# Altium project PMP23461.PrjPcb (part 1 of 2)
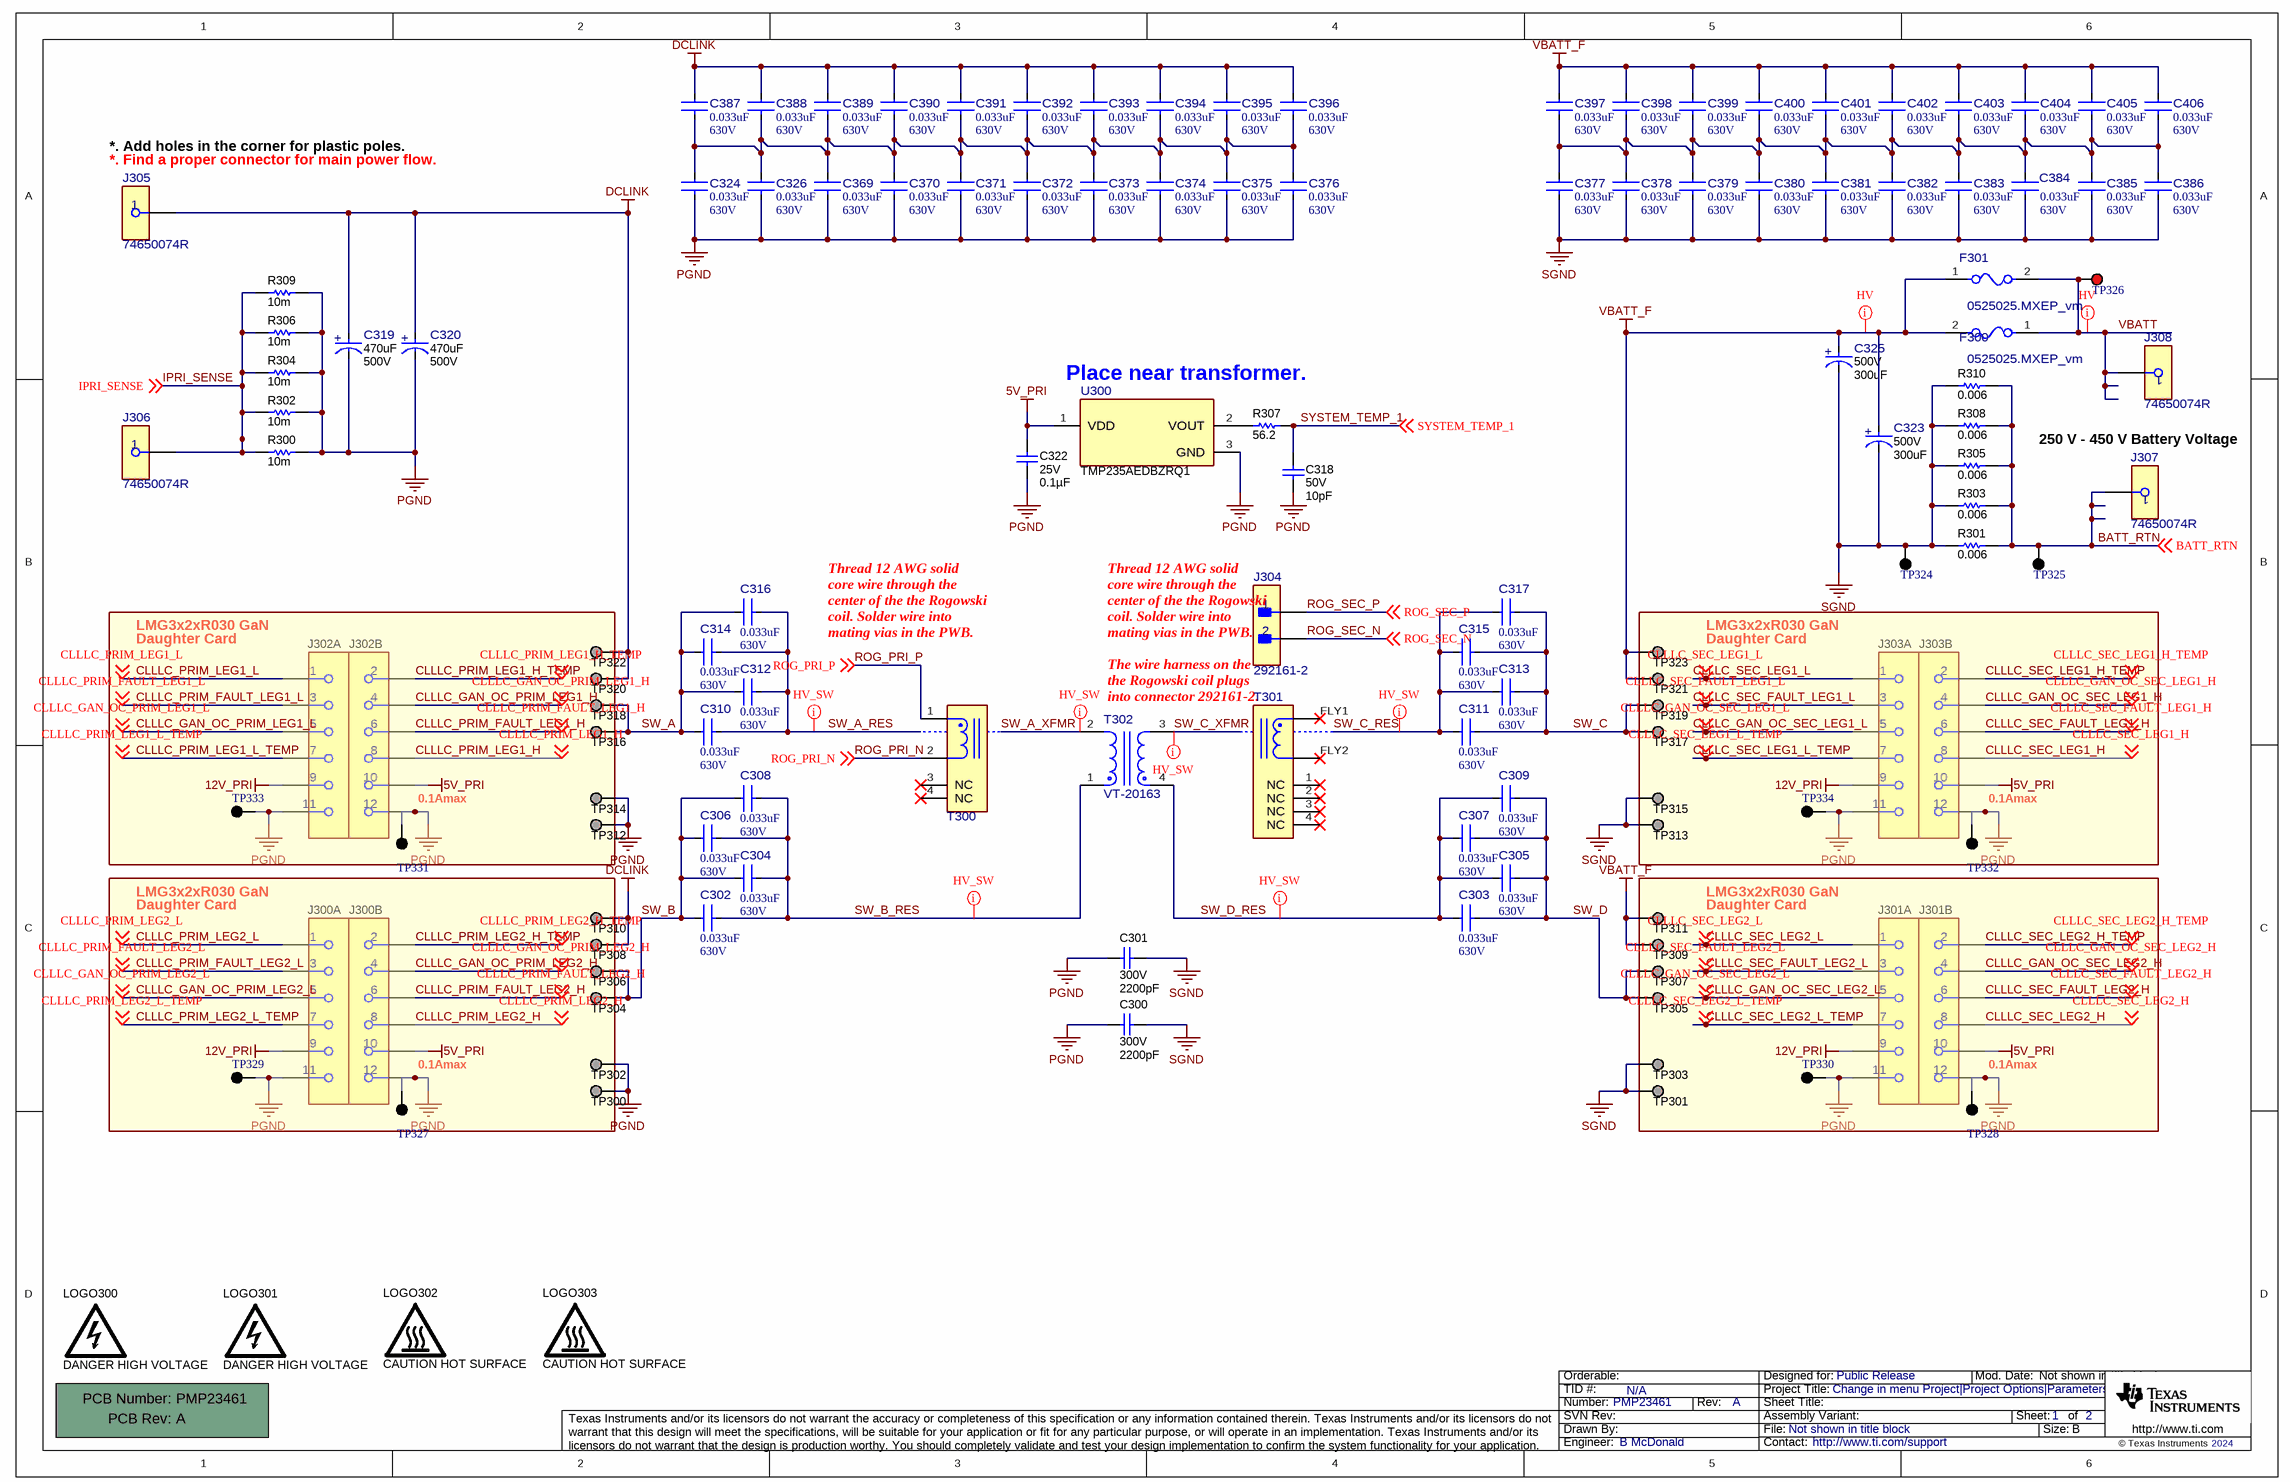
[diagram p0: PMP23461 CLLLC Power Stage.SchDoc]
CopyrightYear: 2024; PCB_Layout: Sean Yu; PCB_Rev: A; PRJ_Customer: Public Release; PRJ_Engineer: B McDonald; PRJ_Number: PMP23461; PRJ_Title: Change in menu Project|Project Options|Parameters; SCH_Rev: A; TechSupport: http://www.ti.com/support; TID: N/A
2 sheets, 242 parts. Net scope: global (net labels, ports and power ports of the same name join across sheets).
Board file: PMP23461 PCB.PcbDoc
Sheets:
  PMP23461 CLLLC Power Stage.SchDoc
  PMP23461 CLLLC Sensing.SchDoc

## Sheet PMP23461 CLLLC Power Stage.SchDoc
size 431 x 279 mm; Date: Not shown in title block; ApprovedBy: Not shown in title block; CheckedBy: Not shown in title block; Author: Not shown in title block; CompanyName: Not shown in title block; Engineer: Not shown in title block; Organization: Not shown in title block; Address1: Not shown in title block; Address2: Not shown in title block; Address3: Not shown in title block; Address4: Not shown in title block; DocumentNumber: 1; Revision: Use project parameter SCH_Rev; SheetNumber: 1; SheetTotal: 2; PageSetup: Record=PageOptions¦CenterHorizontal=True¦CenterVertical=True¦PrintScale=1.00¦XCorrection=1.00¦YCorrection=1.00¦PrintKind=0¦BorderSize=5000000¦LeftOffset=0¦BottomOffset=0¦Orientation=2¦PaperLength=1000¦PaperWidth=1000¦Scale=100¦PaperSource=15¦PrintQuality=600¦MediaType=1¦DitherType=10¦PaperKind=Letter¦PrintScaleMode=1

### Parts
!PCB300  Printed Circuit Board  (value not drawn)  (mechanical)
C300  VDC_V: 300V  ValueDisplayed: 2200pF  [AY2_950x500_Straight]  (hidden comment: AY2222M35Y5US63L7)
C301  VDC_V: 300V  ValueDisplayed: 2200pF  [AY2_950x500_Straight]  (hidden comment: AY2222M35Y5US63L7)
C302  ValueDisplayed: 0.033uF  VDC_V: 630V  [FP-C1210X333JBGACAUTO_1210-MFG]  (hidden comment: CGA6P4C0G2J333J250AA)
C303  ValueDisplayed: 0.033uF  VDC_V: 630V  [FP-C1210X333JBGACAUTO_1210-MFG]  (hidden comment: CGA6P4C0G2J333J250AA)
C304  ValueDisplayed: 0.033uF  VDC_V: 630V  [FP-C1210X333JBGACAUTO_1210-MFG]  (hidden comment: CGA6P4C0G2J333J250AA)
C305  ValueDisplayed: 0.033uF  VDC_V: 630V  [FP-C1210X333JBGACAUTO_1210-MFG]  (hidden comment: CGA6P4C0G2J333J250AA)
C306  ValueDisplayed: 0.033uF  VDC_V: 630V  [FP-C1210X333JBGACAUTO_1210-MFG]  (hidden comment: CGA6P4C0G2J333J250AA)
C307  ValueDisplayed: 0.033uF  VDC_V: 630V  [FP-C1210X333JBGACAUTO_1210-MFG]  (hidden comment: CGA6P4C0G2J333J250AA)
C308  ValueDisplayed: 0.033uF  VDC_V: 630V  [FP-C1210X333JBGACAUTO_1210-MFG]  (hidden comment: CGA6P4C0G2J333J250AA)
C309  ValueDisplayed: 0.033uF  VDC_V: 630V  [FP-C1210X333JBGACAUTO_1210-MFG]  (hidden comment: CGA6P4C0G2J333J250AA)
C310  ValueDisplayed: 0.033uF  VDC_V: 630V  [FP-C1210X333JBGACAUTO_1210-MFG]  (hidden comment: CGA6P4C0G2J333J250AA)
C311  ValueDisplayed: 0.033uF  VDC_V: 630V  [FP-C1210X333JBGACAUTO_1210-MFG]  (hidden comment: CGA6P4C0G2J333J250AA)
C312  ValueDisplayed: 0.033uF  VDC_V: 630V  [FP-C1210X333JBGACAUTO_1210-MFG]  (hidden comment: CGA6P4C0G2J333J250AA)
C313  ValueDisplayed: 0.033uF  VDC_V: 630V  [FP-C1210X333JBGACAUTO_1210-MFG]  (hidden comment: CGA6P4C0G2J333J250AA)
C314  ValueDisplayed: 0.033uF  VDC_V: 630V  [FP-C1210X333JBGACAUTO_1210-MFG]  (hidden comment: CGA6P4C0G2J333J250AA)
C315  ValueDisplayed: 0.033uF  VDC_V: 630V  [FP-C1210X333JBGACAUTO_1210-MFG]  (hidden comment: CGA6P4C0G2J333J250AA)
C316  ValueDisplayed: 0.033uF  VDC_V: 630V  [FP-C1210X333JBGACAUTO_1210-MFG]  (hidden comment: CGA6P4C0G2J333J250AA)
C317  ValueDisplayed: 0.033uF  VDC_V: 630V  [FP-C1210X333JBGACAUTO_1210-MFG]  (hidden comment: CGA6P4C0G2J333J250AA)
C318  VDC_V: 50V  ValueDisplayed: 10pF  [0402]  (hidden comment: 04025U100CAT2A)
C319  ValueDisplayed: 470uF  VDC_V: 500V  [FP-ALA7DA471DE500_RADIAL-MFG]  (hidden comment: B43649A6477M057)
C320  ValueDisplayed: 470uF  VDC_V: 500V  [FP-ALA7DA471DE500_RADIAL-MFG]  (hidden comment: B43649A6477M057)
C322  VDC_V: 25V  ValueDisplayed: 0.1µF  [0402]  (hidden comment: CGA2B3X7R1E104K050BB)
C323  VDC_V: 500V  ValueDisplayed: 300uF  [FP-ALA8DA301CF500_RADIAL-MFG]  (hidden comment: B43649A6337M057)
C324  ValueDisplayed: 0.033uF  VDC_V: 630V  [FP-C1210X333JBGACAUTO_1210-MFG]  (hidden comment: CGA6P4C0G2J333J250AA)
C325  VDC_V: 500V  ValueDisplayed: 300uF  [FP-ALA8DA301CF500_RADIAL-MFG]  (hidden comment: B43649A6337M057)
C326  ValueDisplayed: 0.033uF  VDC_V: 630V  [FP-C1210X333JBGACAUTO_1210-MFG]  (hidden comment: CGA6P4C0G2J333J250AA)
C369  ValueDisplayed: 0.033uF  VDC_V: 630V  [FP-C1210X333JBGACAUTO_1210-MFG]  (hidden comment: CGA6P4C0G2J333J250AA)
C370  ValueDisplayed: 0.033uF  VDC_V: 630V  [FP-C1210X333JBGACAUTO_1210-MFG]  (hidden comment: CGA6P4C0G2J333J250AA)
C371  ValueDisplayed: 0.033uF  VDC_V: 630V  [FP-C1210X333JBGACAUTO_1210-MFG]  (hidden comment: CGA6P4C0G2J333J250AA)
C372  ValueDisplayed: 0.033uF  VDC_V: 630V  [FP-C1210X333JBGACAUTO_1210-MFG]  (hidden comment: CGA6P4C0G2J333J250AA)
C373  ValueDisplayed: 0.033uF  VDC_V: 630V  [FP-C1210X333JBGACAUTO_1210-MFG]  (hidden comment: CGA6P4C0G2J333J250AA)
C374  ValueDisplayed: 0.033uF  VDC_V: 630V  [FP-C1210X333JBGACAUTO_1210-MFG]  (hidden comment: CGA6P4C0G2J333J250AA)
C375  ValueDisplayed: 0.033uF  VDC_V: 630V  [FP-C1210X333JBGACAUTO_1210-MFG]  (hidden comment: CGA6P4C0G2J333J250AA)
C376  ValueDisplayed: 0.033uF  VDC_V: 630V  [FP-C1210X333JBGACAUTO_1210-MFG]  (hidden comment: CGA6P4C0G2J333J250AA)
C377  ValueDisplayed: 0.033uF  VDC_V: 630V  [FP-C1210X333JBGACAUTO_1210-MFG]  (hidden comment: CGA6P4C0G2J333J250AA)
C378  ValueDisplayed: 0.033uF  VDC_V: 630V  [FP-C1210X333JBGACAUTO_1210-MFG]  (hidden comment: CGA6P4C0G2J333J250AA)
C379  ValueDisplayed: 0.033uF  VDC_V: 630V  [FP-C1210X333JBGACAUTO_1210-MFG]  (hidden comment: CGA6P4C0G2J333J250AA)
C380  ValueDisplayed: 0.033uF  VDC_V: 630V  [FP-C1210X333JBGACAUTO_1210-MFG]  (hidden comment: CGA6P4C0G2J333J250AA)
C381  ValueDisplayed: 0.033uF  VDC_V: 630V  [FP-C1210X333JBGACAUTO_1210-MFG]  (hidden comment: CGA6P4C0G2J333J250AA)
C382  ValueDisplayed: 0.033uF  VDC_V: 630V  [FP-C1210X333JBGACAUTO_1210-MFG]  (hidden comment: CGA6P4C0G2J333J250AA)
C383  ValueDisplayed: 0.033uF  VDC_V: 630V  [FP-C1210X333JBGACAUTO_1210-MFG]  (hidden comment: CGA6P4C0G2J333J250AA)
C384  ValueDisplayed: 0.033uF  VDC_V: 630V  [FP-C1210X333JBGACAUTO_1210-MFG]  (hidden comment: CGA6P4C0G2J333J250AA)
C385  ValueDisplayed: 0.033uF  VDC_V: 630V  [FP-C1210X333JBGACAUTO_1210-MFG]  (hidden comment: CGA6P4C0G2J333J250AA)
C386  ValueDisplayed: 0.033uF  VDC_V: 630V  [FP-C1210X333JBGACAUTO_1210-MFG]  (hidden comment: CGA6P4C0G2J333J250AA)
C387  ValueDisplayed: 0.033uF  VDC_V: 630V  [FP-C1210X333JBGACAUTO_1210-MFG]  (hidden comment: CGA6P4C0G2J333J250AA)
C388  ValueDisplayed: 0.033uF  VDC_V: 630V  [FP-C1210X333JBGACAUTO_1210-MFG]  (hidden comment: CGA6P4C0G2J333J250AA)
C389  ValueDisplayed: 0.033uF  VDC_V: 630V  [FP-C1210X333JBGACAUTO_1210-MFG]  (hidden comment: CGA6P4C0G2J333J250AA)
C390  ValueDisplayed: 0.033uF  VDC_V: 630V  [FP-C1210X333JBGACAUTO_1210-MFG]  (hidden comment: CGA6P4C0G2J333J250AA)
C391  ValueDisplayed: 0.033uF  VDC_V: 630V  [FP-C1210X333JBGACAUTO_1210-MFG]  (hidden comment: CGA6P4C0G2J333J250AA)
C392  ValueDisplayed: 0.033uF  VDC_V: 630V  [FP-C1210X333JBGACAUTO_1210-MFG]  (hidden comment: CGA6P4C0G2J333J250AA)
C393  ValueDisplayed: 0.033uF  VDC_V: 630V  [FP-C1210X333JBGACAUTO_1210-MFG]  (hidden comment: CGA6P4C0G2J333J250AA)
C394  ValueDisplayed: 0.033uF  VDC_V: 630V  [FP-C1210X333JBGACAUTO_1210-MFG]  (hidden comment: CGA6P4C0G2J333J250AA)
C395  ValueDisplayed: 0.033uF  VDC_V: 630V  [FP-C1210X333JBGACAUTO_1210-MFG]  (hidden comment: CGA6P4C0G2J333J250AA)
C396  ValueDisplayed: 0.033uF  VDC_V: 630V  [FP-C1210X333JBGACAUTO_1210-MFG]  (hidden comment: CGA6P4C0G2J333J250AA)
C397  ValueDisplayed: 0.033uF  VDC_V: 630V  [FP-C1210X333JBGACAUTO_1210-MFG]  (hidden comment: CGA6P4C0G2J333J250AA)
C398  ValueDisplayed: 0.033uF  VDC_V: 630V  [FP-C1210X333JBGACAUTO_1210-MFG]  (hidden comment: CGA6P4C0G2J333J250AA)
C399  ValueDisplayed: 0.033uF  VDC_V: 630V  [FP-C1210X333JBGACAUTO_1210-MFG]  (hidden comment: CGA6P4C0G2J333J250AA)
C400  ValueDisplayed: 0.033uF  VDC_V: 630V  [FP-C1210X333JBGACAUTO_1210-MFG]  (hidden comment: CGA6P4C0G2J333J250AA)
C401  ValueDisplayed: 0.033uF  VDC_V: 630V  [FP-C1210X333JBGACAUTO_1210-MFG]  (hidden comment: CGA6P4C0G2J333J250AA)
C402  ValueDisplayed: 0.033uF  VDC_V: 630V  [FP-C1210X333JBGACAUTO_1210-MFG]  (hidden comment: CGA6P4C0G2J333J250AA)
C403  ValueDisplayed: 0.033uF  VDC_V: 630V  [FP-C1210X333JBGACAUTO_1210-MFG]  (hidden comment: CGA6P4C0G2J333J250AA)
C404  ValueDisplayed: 0.033uF  VDC_V: 630V  [FP-C1210X333JBGACAUTO_1210-MFG]  (hidden comment: CGA6P4C0G2J333J250AA)
C405  ValueDisplayed: 0.033uF  VDC_V: 630V  [FP-C1210X333JBGACAUTO_1210-MFG]  (hidden comment: CGA6P4C0G2J333J250AA)
C406  ValueDisplayed: 0.033uF  VDC_V: 630V  [FP-C1210X333JBGACAUTO_1210-MFG]  (hidden comment: CGA6P4C0G2J333J250AA)
F300  0525025.MXEP_vm  [FP-0525025.MXEP_vm_AXIAL-MFG]
F301  0525025.MXEP_vm  [FP-0525025.MXEP_vm_AXIAL-MFG]
J300  HLE-106-02-G-DV-BE-A  [FP-HLE-106-02-G-DV-BE-A_HDR12-MFG]  (value not drawn)  (parts A,B of 2)
J301  HLE-106-02-G-DV-BE-A  [FP-HLE-106-02-G-DV-BE-A_HDR12-MFG]  (value not drawn)  (parts A,B of 2)
J302  HLE-106-02-G-DV-BE-A  [FP-HLE-106-02-G-DV-BE-A_HDR12-MFG]  (value not drawn)  (parts A,B of 2)
J303  HLE-106-02-G-DV-BE-A  [FP-HLE-106-02-G-DV-BE-A_HDR12-MFG]  (value not drawn)  (parts A,B of 2)
J304  292161-2  [FP-292161-2_HDR2-MFG]
J305  74650074R  [FP-74650074R_SCREW_MOUNTING-MFG]
J306  74650074R  [FP-74650074R_SCREW_MOUNTING-MFG]
J307  74650074R  [FP-74650074R_SCREW_MOUNTING-MFG]
J308  74650074R  [FP-74650074R_SCREW_MOUNTING-MFG]
LOGO300  DANGER HIGH VOLTAGE  [IEC_HighVoltage_Small]  (no BOM)
LOGO301  DANGER HIGH VOLTAGE  [IEC_HighVoltage_Small]  (no BOM)
LOGO302  CAUTION HOT SURFACE  [IEC_HotSurface_Small]  (no BOM)
LOGO303  CAUTION HOT SURFACE  [IEC_HotSurface_Small]  (no BOM)
R300  ValueDisplayed: 10m  [FP-CRF1206-FZ-R010ELF_1206-MFG]  (hidden comment: CRF1206-FZ-R010ELF)
R301  ValueDisplayed: 0.006  [1206]  (hidden comment: WSL12066L000FEA18)
R302  ValueDisplayed: 10m  [FP-CRF1206-FZ-R010ELF_1206-MFG]  (hidden comment: CRF1206-FZ-R010ELF)
R303  ValueDisplayed: 0.006  [1206]  (hidden comment: WSL12066L000FEA18)
R304  ValueDisplayed: 10m  [FP-CRF1206-FZ-R010ELF_1206-MFG]  (hidden comment: CRF1206-FZ-R010ELF)
R305  ValueDisplayed: 0.006  [1206]  (hidden comment: WSL12066L000FEA18)
R306  ValueDisplayed: 10m  [FP-CRF1206-FZ-R010ELF_1206-MFG]  (hidden comment: CRF1206-FZ-R010ELF)
R307  ValueDisplayed: 56.2  [0402]  (hidden comment: CRCW040256R2FKED)
R308  ValueDisplayed: 0.006  [1206]  (hidden comment: WSL12066L000FEA18)
R309  ValueDisplayed: 10m  [FP-CRF1206-FZ-R010ELF_1206-MFG]  (hidden comment: CRF1206-FZ-R010ELF)
R310  ValueDisplayed: 0.006  [1206]  (hidden comment: WSL12066L000FEA18)
T300  RLTI-1371  [FP-RLTI-1371_PTH_XFRMR_0IN828_0IN300-MFG]  (value not drawn)
T301  RLTI-1379  [FP-RLTI-1379_PTH_XFRMR_0IN828_0IN300-MFG]  (value not drawn)
T302  VT-20163  [FP-VT-20163_PTH_TRANSFORMER_73MM0_51MM0-MFG]
TP300  0312-0-15-15-34-27-10-0  [Mill-Max_0312-0-15-15-34-27-10-0]  (value not drawn)
TP301  0312-0-15-15-34-27-10-0  [Mill-Max_0312-0-15-15-34-27-10-0]  (value not drawn)
TP302  0312-0-15-15-34-27-10-0  [Mill-Max_0312-0-15-15-34-27-10-0]  (value not drawn)
TP303  0312-0-15-15-34-27-10-0  [Mill-Max_0312-0-15-15-34-27-10-0]  (value not drawn)
TP304  0312-0-15-15-34-27-10-0  [Mill-Max_0312-0-15-15-34-27-10-0]  (value not drawn)
TP305  0312-0-15-15-34-27-10-0  [Mill-Max_0312-0-15-15-34-27-10-0]  (value not drawn)
TP306  0312-0-15-15-34-27-10-0  [Mill-Max_0312-0-15-15-34-27-10-0]  (value not drawn)
TP307  0312-0-15-15-34-27-10-0  [Mill-Max_0312-0-15-15-34-27-10-0]  (value not drawn)
TP308  0312-0-15-15-34-27-10-0  [Mill-Max_0312-0-15-15-34-27-10-0]  (value not drawn)
TP309  0312-0-15-15-34-27-10-0  [Mill-Max_0312-0-15-15-34-27-10-0]  (value not drawn)
TP310  0312-0-15-15-34-27-10-0  [Mill-Max_0312-0-15-15-34-27-10-0]  (value not drawn)
TP311  0312-0-15-15-34-27-10-0  [Mill-Max_0312-0-15-15-34-27-10-0]  (value not drawn)
TP312  0312-0-15-15-34-27-10-0  [Mill-Max_0312-0-15-15-34-27-10-0]  (value not drawn)
TP313  0312-0-15-15-34-27-10-0  [Mill-Max_0312-0-15-15-34-27-10-0]  (value not drawn)
TP314  0312-0-15-15-34-27-10-0  [Mill-Max_0312-0-15-15-34-27-10-0]  (value not drawn)
TP315  0312-0-15-15-34-27-10-0  [Mill-Max_0312-0-15-15-34-27-10-0]  (value not drawn)
TP316  0312-0-15-15-34-27-10-0  [Mill-Max_0312-0-15-15-34-27-10-0]  (value not drawn)
TP317  0312-0-15-15-34-27-10-0  [Mill-Max_0312-0-15-15-34-27-10-0]  (value not drawn)
TP318  0312-0-15-15-34-27-10-0  [Mill-Max_0312-0-15-15-34-27-10-0]  (value not drawn)
TP319  0312-0-15-15-34-27-10-0  [Mill-Max_0312-0-15-15-34-27-10-0]  (value not drawn)
TP320  0312-0-15-15-34-27-10-0  [Mill-Max_0312-0-15-15-34-27-10-0]  (value not drawn)
TP321  0312-0-15-15-34-27-10-0  [Mill-Max_0312-0-15-15-34-27-10-0]  (value not drawn)
TP322  0312-0-15-15-34-27-10-0  [Mill-Max_0312-0-15-15-34-27-10-0]  (value not drawn)
TP323  0312-0-15-15-34-27-10-0  [Mill-Max_0312-0-15-15-34-27-10-0]  (value not drawn)
TP324  5001  [Keystone5001]  (value not drawn)
TP325  5001  [Keystone5001]  (value not drawn)
TP326  5000  [Keystone5000]  (value not drawn)
TP327  5001  [Keystone5001]  (value not drawn)
TP328  5001  [Keystone5001]  (value not drawn)
TP329  5001  [Keystone5001]  (value not drawn)
TP330  5001  [Keystone5001]  (value not drawn)
TP331  5001  [Keystone5001]  (value not drawn)
TP332  5001  [Keystone5001]  (value not drawn)
TP333  5001  [Keystone5001]  (value not drawn)
TP334  5001  [Keystone5001]  (value not drawn)
U300  TMP235AEDBZRQ1  [DBZ0003A-MFG]

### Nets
5V_PRI: C322.1 J300.10 J301.10 J302.10 J303.10 U300.1(VDD)
12V_PRI: J300.9 J301.9 J302.9 J303.9
DCLINK: C319.2(ANODE) C320.2(ANODE) C387.1 C388.1 C389.1 C390.1 C391.1 C392.1 C393.1 C394.1 C395.1 C396.1 J305.1 TP308.1 TP310.1 TP320.1 TP322.1
PGND: C300.2 C301.2 C318.2 C319.1(CATHODE) C320.1(CATHODE) C322.2 C324.2 C326.2 C369.2 C370.2 C371.2 C372.2 C373.2 C374.2 C375.2 C376.2 J300.11 J300.12 J301.11 J301.12 J302.11 J302.12 J303.11 J303.12 R300.2 R302.2 R304.2 R306.2 R309.2 TP300.1 TP302.1 TP312.1 TP314.1 TP327.1 TP328.1 TP329.1 TP330.1 TP331.1 TP332.1 TP333.1 TP334.1 U300.3(GND)
SGND: C300.1 C301.1 C323.1(CATHODE) C325.1(CATHODE) C377.2 C378.2 C379.2 C380.2 C381.2 C382.2 C383.2 C384.2 C385.2 C386.2 R301.1 R303.1 R305.1 R308.1 R310.1 TP301.1 TP303.1 TP313.1 TP315.1 TP324.1
VBATT_F: C323.2(ANODE) C325.2(ANODE) C397.1 C398.1 C399.1 C400.1 C401.1 C402.1 C403.1 C404.1 C405.1 C406.1 F300.2 F301.1 TP309.1 TP311.1 TP321.1 TP323.1
BATT_RTN: J307.1 R301.2 R303.2 R305.2 R308.2 R310.2 TP325.1 ; off-sheet BATT_RTN
CLLLC_GAN_OC_PRIM_LEG1_H: J302.4 ; off-sheet CLLLC_GAN_OC_PRIM_LEG1_H
CLLLC_GAN_OC_PRIM_LEG1_L: J302.5 ; off-sheet CLLLC_GAN_OC_PRIM_LEG1_L
CLLLC_GAN_OC_PRIM_LEG2_H: J300.4 ; off-sheet CLLLC_GAN_OC_PRIM_LEG2_H
CLLLC_GAN_OC_PRIM_LEG2_L: J300.5 ; off-sheet CLLLC_GAN_OC_PRIM_LEG2_L
CLLLC_GAN_OC_SEC_LEG1_H: J303.4 ; off-sheet CLLLC_GAN_OC_SEC_LEG1_H
CLLLC_GAN_OC_SEC_LEG1_L: J303.5 ; off-sheet CLLLC_GAN_OC_SEC_LEG1_L
CLLLC_GAN_OC_SEC_LEG2_H: J301.4 ; off-sheet CLLLC_GAN_OC_SEC_LEG2_H
CLLLC_GAN_OC_SEC_LEG2_L: J301.5 ; off-sheet CLLLC_GAN_OC_SEC_LEG2_L
CLLLC_PRIM_FAULT_LEG1_H: J302.6 ; off-sheet CLLLC_PRIM_FAULT_LEG1_H
CLLLC_PRIM_FAULT_LEG1_L: J302.3 ; off-sheet CLLLC_PRIM_FAULT_LEG1_L
CLLLC_PRIM_FAULT_LEG2_H: J300.6 ; off-sheet CLLLC_PRIM_FAULT_LEG2_H
CLLLC_PRIM_FAULT_LEG2_L: J300.3 ; off-sheet CLLLC_PRIM_FAULT_LEG2_L
CLLLC_PRIM_LEG1_H: J302.8 ; off-sheet CLLLC_PRIM_LEG1_H
CLLLC_PRIM_LEG1_H_TEMP: J302.2 ; off-sheet CLLLC_PRIM_LEG1_H_TEMP
CLLLC_PRIM_LEG1_L: J302.1 ; off-sheet CLLLC_PRIM_LEG1_L
CLLLC_PRIM_LEG1_L_TEMP: J302.7 ; off-sheet CLLLC_PRIM_LEG1_L_TEMP
CLLLC_PRIM_LEG2_H: J300.8 ; off-sheet CLLLC_PRIM_LEG2_H
CLLLC_PRIM_LEG2_H_TEMP: J300.2 ; off-sheet CLLLC_PRIM_LEG2_H_TEMP
CLLLC_PRIM_LEG2_L: J300.1 ; off-sheet CLLLC_PRIM_LEG2_L
CLLLC_PRIM_LEG2_L_TEMP: J300.7 ; off-sheet CLLLC_PRIM_LEG2_L_TEMP
CLLLC_SEC_FAULT_LEG1_H: J303.6 ; off-sheet CLLLC_SEC_FAULT_LEG1_H
CLLLC_SEC_FAULT_LEG1_L: J303.3 ; off-sheet CLLLC_SEC_FAULT_LEG1_L
CLLLC_SEC_FAULT_LEG2_H: J301.6 ; off-sheet CLLLC_SEC_FAULT_LEG2_H
CLLLC_SEC_FAULT_LEG2_L: J301.3 ; off-sheet CLLLC_SEC_FAULT_LEG2_L
CLLLC_SEC_LEG1_H: J303.8 ; off-sheet CLLLC_SEC_LEG1_H
CLLLC_SEC_LEG1_H_TEMP: J303.2 ; off-sheet CLLLC_SEC_LEG1_H_TEMP
CLLLC_SEC_LEG1_L: J303.1 ; off-sheet CLLLC_SEC_LEG1_L
CLLLC_SEC_LEG1_L_TEMP: J303.7 ; off-sheet CLLLC_SEC_LEG1_L_TEMP
CLLLC_SEC_LEG2_H: J301.8 ; off-sheet CLLLC_SEC_LEG2_H
CLLLC_SEC_LEG2_H_TEMP: J301.2 ; off-sheet CLLLC_SEC_LEG2_H_TEMP
CLLLC_SEC_LEG2_L: J301.1 ; off-sheet CLLLC_SEC_LEG2_L
CLLLC_SEC_LEG2_L_TEMP: J301.7 ; off-sheet CLLLC_SEC_LEG2_L_TEMP
IPRI_SENSE: J306.1 R300.1 R302.1 R304.1 R306.1 R309.1 ; off-sheet IPRI_SENSE
ROG_PRI_N: T300.2 ; off-sheet ROG_PRI_N
ROG_PRI_P: T300.1 ; off-sheet ROG_PRI_P
ROG_SEC_N: J304.2 ; off-sheet ROG_SEC_N
ROG_SEC_P: J304.1 ; off-sheet ROG_SEC_P
SW_A: C310.1 C312.1 C314.1 C316.1 TP316.1 TP318.1
SW_A_RES: C310.2 C312.2 C314.2 C316.2
SW_A_XFMR: T302.2
SW_B: C302.1 C304.1 C306.1 C308.1 TP304.1 TP306.1
SW_B_RES: C302.2 C304.2 C306.2 C308.2 T302.1
SW_C: C311.2 C313.2 C315.2 C317.2 TP317.1 TP319.1
SW_C_RES: C311.1 C313.1 C315.1 C317.1
SW_C_XFMR: T302.3
SW_D: C303.2 C305.2 C307.2 C309.2 TP305.1 TP307.1
SW_D_RES: C303.1 C305.1 C307.1 C309.1 T302.4
SYSTEM_TEMP_1: C318.1 R307.2 ; off-sheet SYSTEM_TEMP_1
VBATT: F300.1 F301.2 J308.1 TP326.1
NetC324_1: C324.1 C326.1 C369.1 C370.1 C371.1 C372.1 C373.1 C374.1 C375.1 C376.1 C387.2 C388.2 C389.2 C390.2 C391.2 C392.2 C393.2 C394.2 C395.2 C396.2
NetC377_1: C377.1 C378.1 C379.1 C380.1 C381.1 C382.1 C383.1 C384.1 C385.1 C386.1 C397.2 C398.2 C399.2 C400.2 C401.2 C402.2 C403.2 C404.2 C405.2 C406.2
NetR307_1: R307.1 U300.2(VOUT)

Not connected (* = marked no-connect by the designer): T300 3(NC)* 4(NC)*; T301 1(NC)* 2(NC)* 3(NC)* 4(NC)*

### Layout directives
net class HV: VBATT, VBATT_F
net class HV_SW: SW_A_RES, SW_A_XFMR, SW_B_RES, SW_C_RES, SW_C_XFMR, SW_D_RES

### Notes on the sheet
- (near J305) *. Find a proper connector for main power flow.
- *. Add holes in the corner for plastic poles.
- Place near transformer.
- 250 V - 450 V Battery Voltage
- LMG3x2xR030 GaN
- Daughter Card
- Thread 12 AWG solid core wire through the center of the the Rogowski coil. Solder wire into mating vias in the PWB.
- (near T302) Thread 12 AWG solid core wire through the center of the the Rogowski coil. Solder wire into mating vias in the PWB.
  The wire harness on the the Rogowski coil plugs into connector 292161-2.
- 0.1Amax

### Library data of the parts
!PCB300 = CMP-0003618-2: Manufacturer: Any; PartNumber: PMP23461
C300 C301 = CMP-0009587-2: CAP, CERM, 2200 pF, 300 V, +/- 20%, Y5U, AEC-Q200 Grade 1, D9.5xT5mm; Manufacturer: Vishay-Bccomponents; TaMin_C: -55°C; Polarized: N; SizeAreaWB_mm2: 80.5; Value1: Unknown; U/M: EA; Value: 2200pF; TaMax_C: 125°C; SizeZ_mm: 14.5; SizeX_mm: 9.5; SizeY_mm: 5; Cap_Case: 9.5x5mm; SizeArea_mm2: 47.5; AEC Qualified: Y; Cap_F: 2.2nF; AEC Grade: 1; AEC Category: Q200
C302-C317 C324 C326 C369-C406 = CMP-0090696-1: 0.033µF ±5% 630V Ceramic Capacitor C0G, NP0 1210 (3225 Metric); Manufacturer: TDK; Cap_F: 33nF; SizeZ_mm: 2.8mm; TempCo: 30ppm/°C; AEC Qualified: Yes; Value: 33nF; AEC Grade: Grade 1
C318 = CMP-0064911-2: CAP, CERM, 10 pF, 50 V,+/- 2.5%, C0G/NP0, AEC-Q200 Grade 1, 0402; Manufacturer: AVX; TaMin_C: -55°C; Polarized: N; SizeAreaWB_mm2: 3; Value1: Unknown; U/M: EA; Value: 10pF; TaMax_C: 125°C; SizeZ_mm: 0.6; SizeX_mm: 1; SizeY_mm: 0.5; AEC Qualified: Y; AEC Category: Q200
C319 C320 = CMP-0090234-1: 470µF 500V Aluminum Electrolytic Capacitors Radial, Can - Snap-In 532.2mOhm @ 100Hz 15000 Hrs @ 85°C; Manufacturer: TDK; Leakage Current: 6uA; SizeZ_mm: 47mm; IRMS_A: 4.6A; Life: 15000Hours; Tolerance_%: 20%; AEC Grade: Grade 3; Esr: 0.532; AEC Qualified: Yes
C322 = CMP-0080610-1: CAP, CERM, 0.1 µF, 25 V,+/- 10%, X7R, AEC-Q200 Grade 1, 0402; Manufacturer: TDK; TaMin_C: -55°C; Polarized: N; SizeAreaWB_mm2: 3; U/M: EA; Value: 0.1uF; TaMax_C: 125°C; SizeZ_mm: 0.6; SizeX_mm: 1; SizeY_mm: 0.5; AEC Qualified: Y; Cap_F: 100nF; AEC Category: Q200
C323 C325 = CMP-0090464-1: 300µF 500V Aluminum Electrolytic Capacitors Radial, Can - Snap-In 687.4mOhm @ 100Hz 7000 Hrs @ 105°C; Manufacturer: TDK; Tolerance_%: 20%; AEC Qualified: Yes; Esr: 0.687; Leakage Current: 450uA; Life: 11000Hours; AEC Grade: Grade 2; SizeZ_mm: 52mm; IRMS_A: 4.8A
F300 F301 = CMP-4956-0000-1: 25A AC 450V DC Fuse Cartridge, Ceramic Through Hole 3AB, 3AG, 1/4" x 1-1/4" (Axial); Manufacturer: Littelfuse; AEC Grade: NA; Fuse Interrupt Dc Current: 10000A; AEC Qualified: No; Res_ohm: 3.8mΩ; MeltingTyp: 320A2Sec; Interrupt_DC: 10kA
J300-J303 = CMP-0089984-1: 12 Position Receptacle, Bottom Entry Connector  Surface Mount; Manufacturer: Samtec; Current_A: 4.1A; Conn Orientation: Vertical; DUT-Pitch_mm: 2.54mm; Conn Gender: Female; SizeZ_mm: 3.79mm; Is Female: yes; AEC Qualified: No; ContactFinish: Gold,Nickel; Voltage_V: 400V; Row_Count: 2
J304 = CMP-0090793-1: Connector Header Through Hole 2 position 0.079" (2.00mm); Manufacturer: TE Connectivity; Current_A: 4A; Conn Orientation: Vertical; SizeZ_mm: 7mm; Conn Gender: Male; Row_Count: 1; DUT-Pitch_mm: 2mm; Voltage_V: 125V; ContactFinish: Tin,Nickel; AEC Qualified: No
J305-J308 = CMP-0086784-1: 4 Pin Screw Terminal, Power Tap M4 Through Hole; Manufacturer: Würth Elektronik; SizeZ_mm: 3mm
LOGO300 LOGO301 = CMP-0074835-1: IEC 61010-1 High Voltage Warning; SymbolCreator: a0412235
LOGO302 LOGO303 = CMP-0074837-1: IEC 61010-1 Hot Surface Warning; SymbolCreator: a0412235
R300 R302 R304 R306 R309 = CMP-0086941-2: 10 mOhms ±1% 1W Chip Resistor 1206 (3216 Metric) Automotive AEC-Q200, Current Sense, Moisture Resistant Metal Element; Manufacturer: Bourns; AEC Qualified: Yes; TempCo: 50ppm/°C; AEC Grade: Grade 0; Res_ohm: 0.01; SizeZ_mm: 0.8mm
R301 R303 R305 R308 R310 = CMP-0018567-2: RES, 0.006, 1%, 0.5 W, 1206; Manufacturer: Vishay-Dale; Power_W: 500mW; TempCo: 110 ppm/C; Value_Code: 6L000; U/M: EA; Value: 0.006; EIA_Code: E96; Res_ohm: 6m; SizeX_mm: 3.2; SizeY_mm: 1.6; SizeZ_mm: 1.35; Value2: 0.5W; SizeArea_mm2: 5.12; AEC Category: Q200
R307 = CMP-0026454-2: RES, 56.2, 1%, 0.063 W, AEC-Q200 Grade 0, 0402; Manufacturer: Vishay-Dale; Power_W: 63mW; TempCo: 100 ppm/C; Value_Code: 56R2; Value: 56.2; EIA_Code: E96; SizeX_mm: 1; SizeY_mm: 0.5; SizeZ_mm: 0.6; Value2: 0.063W; AEC Qualified: Y; VDC_V: 50V; AEC Category: Q200; AEC Grade: 0
T300 = CMP-0090959-1: PRIMARY SIDE ROGOWSKI (PMP22495); Manufacturer: Renco Electronics; SizeZ_mm: 0.938inch; AEC Qualified: No; Ind_H: 6.3µH; DCR_ohm: 1.2
T301 = CMP-0090960-2: Secondary Side Rogowski (PMP22495); Manufacturer: Renco Electronics; Ind_H: 6.3µH; SizeZ_mm: 0.938inch; AEC Qualified: No; DCR_ohm: 1.2
T302 = CMP-0090781-3: TRANSFORMER; Manufacturer: Cyntec; DCR_ohm: 9.6m; Ind_H: 16µH; Voltage_Isolation_Vrms: 2000VDC; Rsec1_ohm: 7.4m; AEC Qualified: Unknown
TP300-TP323 = CMP-0055026-1: Manufacturer: Mill-Max; CNHeader: FALSE; Green_Lifecycle: Active; Gender: Female; Green_REACh: Passed; CompType: Pin Receptacle; ContactFinish: Gold
TP324 TP325 = CMP-0055138-1: Test Point, Miniature, Black, TH; Manufacturer: Keystone; CNHeader: FALSE; Green_Lifecycle: Active; Green_REACh: Passed; ContactFinish: Silver; CT: TRUE
TP326 = CMP-0055137-1: Test Point, Miniature, Red, TH; Manufacturer: Keystone; CNHeader: FALSE; Green_Lifecycle: Active; Green_REACh: Passed; ContactFinish: Silver; CT: TRUE
TP327-TP334 = CMP-0055138-2: Test Point, Miniature, Black, TH; Manufacturer: Keystone Electronics; ContactFinish: Silver; CNHeader: FALSE; Green_Lifecycle: Active; Green_REACh: Passed; CT: TRUE
U300 = CMP-0090472-1: Temperature Sensor Analog, Local -40°C ~ 150°C 10mV/°C SOT-23-3; Manufacturer: Texas Instruments; TJmax_C: +150°C; Min Supply Voltage: 2.3V; SizeZ_mm: 1.12mm; Max Supply Voltage: 5.5V; Interface: Other; AEC Qualified: Yes; Output Voltage: 500mV; AEC Grade: Grade 0; Standoff Height: 0.01mm; Sensor Output: Analog Voltage; Operating Supply Current: 9uA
